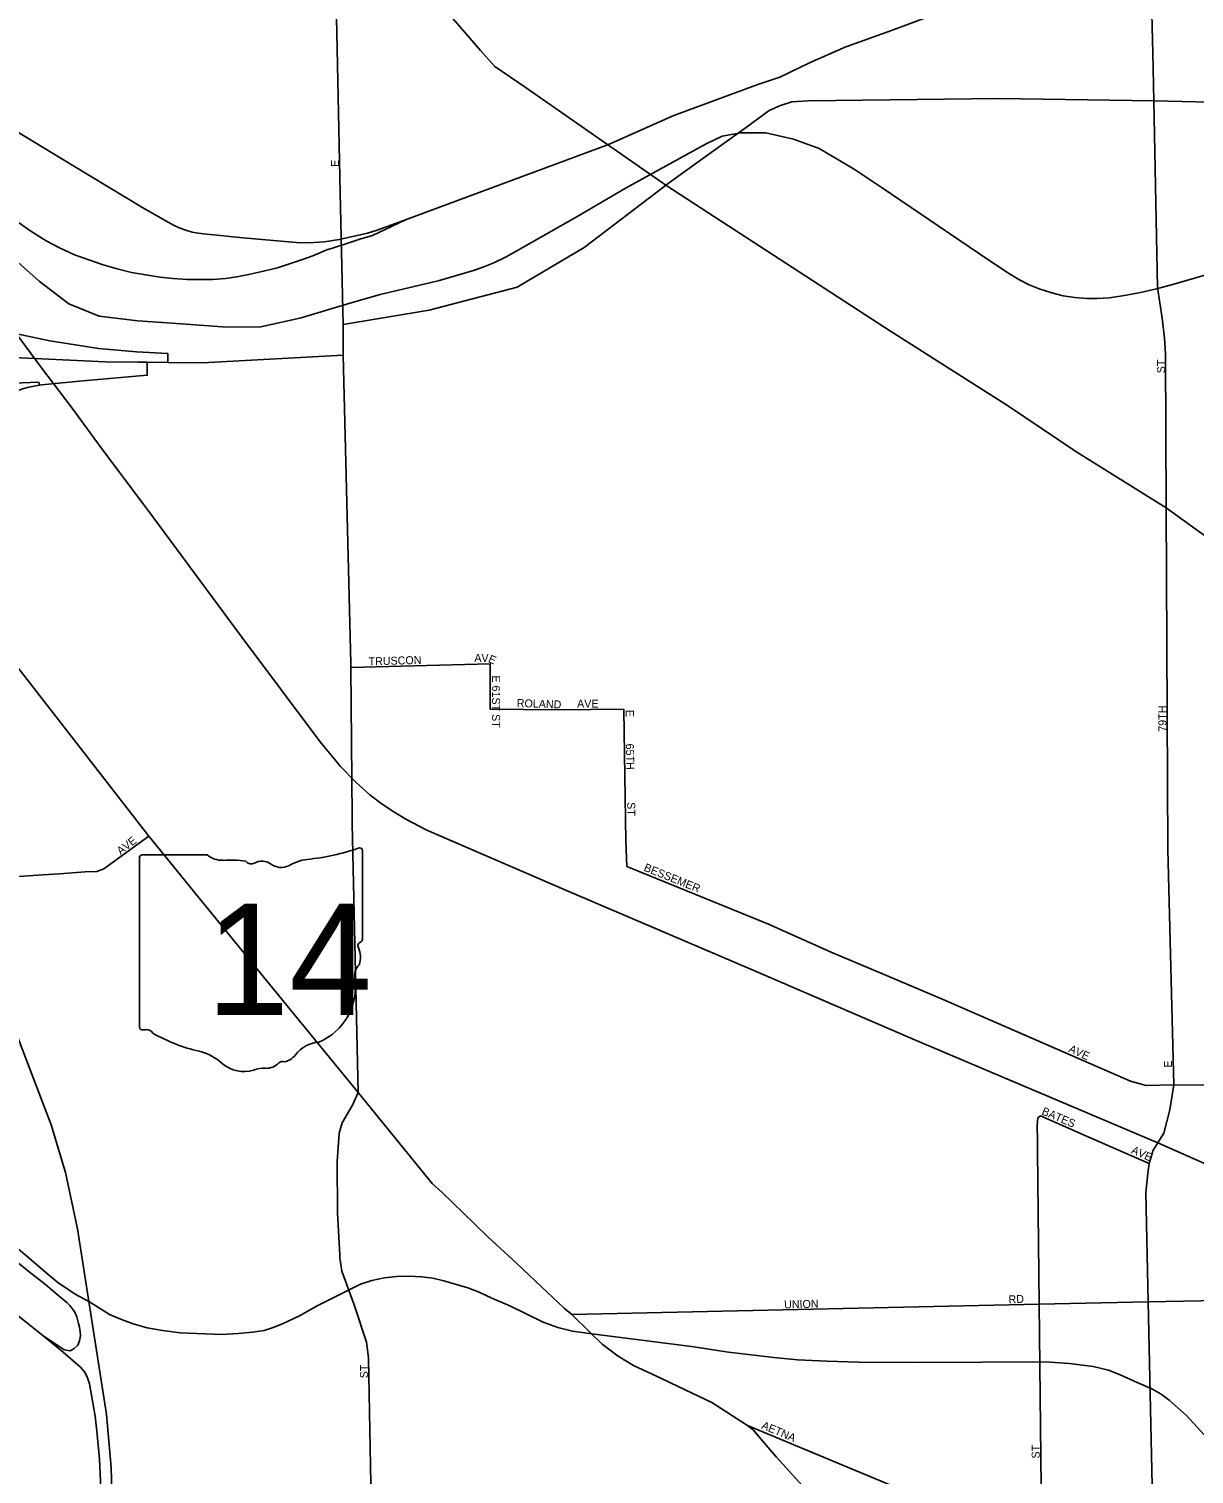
# Model space of a CAD drawing. Extents: x -561 to 1170, y 0 to 846.
# Drawn here: x 268.18 to 287.84, y 250.97 to 275.35 of the extents above; entities that cross this region are included whole.
import ezdxf

# ---------------------------------------------------------------- set-up
doc = ezdxf.new("R2010")
doc.units = 0
for name, color, linetype in [('GM_P_County_Alignment', 7, 'Continuous'), ('GM_X_City_Street', 7, 'Continuous'), ('GM_X_City_Street_Text', 7, 'Continuous'), ('GM_X_Interchange_Ramps', 7, 'Continuous'), ('GM_X_Interstate_Route', 7, 'Continuous'), ('GM_X_Rail_Line', 7, 'Continuous'), ('GM_X_State_Location', 7, 'Continuous'), ('GM_X_State_Route', 7, 'Continuous'), ('GM_X_State_Shield', 7, 'Continuous'), ('GM_X_US_Route', 7, 'Continuous')]:
    doc.layers.add(name, color=color, linetype=linetype)

msp = doc.modelspace()

# ---------------------------------------------------------------- linework, layer by layer
at = {"layer": 'GM_P_County_Alignment'}
msp.add_lwpolyline([(273.482, 270.361), (274.932, 270.603), (276.416, 270.991), (277.547, 271.663), (278.891, 272.688), (278.927, 272.714), (279.692, 273.264), (279.991, 273.477), (280.288, 273.69), (280.673, 273.973), (280.863, 274.059), (281.053, 274.12), (281.33, 274.137), (284.546, 274.173), (287.159, 274.138), (290.025, 274.067)], dxfattribs=at)
at = {"layer": 'GM_X_City_Street'}
for points in [[(273.434, 272.587), (273.318, 277.977), (273.132, 283.304), (273.037, 286.052), (272.983, 290.301), (272.97, 291.367), (272.969, 291.404)], [(287.498, 257.536), (287.498, 257.538), (287.397, 261.505), (287.369, 267.269), (287.36, 269.871), (287.343, 270.131), (287.3, 270.469), (287.222, 270.99), (287.159, 274.138), (287.144, 274.945), (287.117, 276.052), (287.06, 276.294), (286.946, 276.667), (286.888, 276.901), (286.871, 277.102), (286.807, 278.301)], [(273.477, 270.601), (273.434, 272.587)], [(273.61, 264.643), (273.485, 269.848), (273.485, 270.248), (273.482, 270.361), (273.477, 270.601)], [(273.634, 261.948), (273.632, 262.064), (273.611, 264.577), (273.61, 264.643)], [(273.611, 264.577), (275.965, 264.642), (275.965, 264.588)], [(275.965, 264.588), (275.965, 263.879)], [(275.965, 263.879), (275.965, 263.877), (277.091, 263.866), (278.217, 263.872), (278.217, 263.857)], [(278.217, 263.857), (278.252, 261.653), (278.271, 261.221), (278.323, 261.2)], [(273.734, 257.409), (273.634, 261.948)], [(268.695, 261.098), (269.132, 261.128), (269.329, 261.135), (269.446, 261.179), (270.203, 261.73)], [(268.413, 261.079), (268.695, 261.098)], [(278.323, 261.2), (280.659, 260.248), (281.726, 259.772), (282.649, 259.381), (283.618, 258.973), (286.765, 257.597), (287.032, 257.527), (287.498, 257.538)], [(267.409, 261.011), (267.849, 261.041), (268.413, 261.079)], [(287.498, 257.538), (288.021, 257.534), (288.387, 257.543), (289.954, 257.593), (290.044, 257.561), (290.116, 257.459), (291.558, 257.465), (291.591, 256.492), (291.643, 256.424), (292.109, 256.444), (292.519, 256.456), (292.475, 257.061), (292.399, 258.101), (295.762, 258.143)], [(287.062, 256.042), (287.079, 256.211), (287.15, 256.436), (287.329, 256.725), (287.43, 257.117), (287.498, 257.536)], [(273.41, 256.638), (273.416, 256.722), (273.464, 256.896), (273.638, 257.197), (273.734, 257.409)], [(285.196, 256.602), (285.192, 256.854), (285.206, 256.979), (285.248, 257.017), (285.581, 256.871), (286.022, 256.672), (287.079, 256.211)], [(273.425, 254.67), (273.387, 255.371), (273.38, 256.252), (273.41, 256.638)], [(285.27, 249.584), (285.269, 249.71), (285.226, 253.84), (285.199, 256.421), (285.197, 256.519), (285.196, 256.602)], [(287.271, 244.073), (287.898, 245.662), (288.224, 246.528), (288.348, 246.925), (288.028, 247.986), (287.735, 248.712), (287.704, 248.928), (287.735, 249.015), (287.559, 249.234), (287.156, 249.747), (287.067, 253.877), (287.027, 255.72), (287.062, 256.042)], [(273.879, 253.196), (273.879, 253.199), (273.667, 253.827), (273.462, 254.393), (273.428, 254.619), (273.425, 254.67)], [(277.34, 253.662), (285.226, 253.84), (287.067, 253.877), (289.452, 253.925)], [(273.951, 250.806), (273.913, 252.932), (273.879, 253.196)], [(280.304, 251.79), (284.72, 249.952), (285.269, 249.71), (285.314, 249.691), (287.156, 249.747), (288.56, 249.78), (288.562, 249.78)]]:
    msp.add_lwpolyline(points, dxfattribs=at)
at = {"layer": 'GM_X_Interchange_Ramps'}
for points in [[(270.524, 269.724), (270.525, 269.874), (269.995, 269.9), (269.355, 269.961), (268.535, 270.087), (267.65, 270.275), (267.595, 270.287), (267.328, 270.389), (267.108, 270.51), (266.895, 270.656), (266.715, 270.825), (266.549, 271.01), (266.388, 271.244), (266.133, 271.647), (265.699, 272.333), (265.393, 272.845), (265.269, 273.105), (265.17, 273.315), (265.054, 273.576), (264.924, 273.967), (264.838, 273.944)], [(265.022, 271.942), (265.072, 271.942), (265.096, 271.624), (265.139, 271.391), (265.208, 271.132), (265.283, 270.902), (265.389, 270.647), (265.503, 270.453), (265.623, 270.282), (265.756, 270.126), (265.924, 269.978), (265.945, 269.959), (266.014, 269.898), (266.078, 269.841), (266.289, 269.701), (266.485, 269.621), (266.683, 269.556), (266.895, 269.489), (267.177, 269.423), (267.447, 269.391), (267.772, 269.363), (268.069, 269.379), (268.35, 269.388), (268.359, 269.34)], [(266.892, 265.84), (266.998, 265.854), (267.011, 265.855), (266.997, 266.151), (266.952, 266.952), (266.942, 267.44), (266.943, 267.633), (266.944, 267.778), (266.968, 268.061), (267.027, 268.301), (267.101, 268.47), (267.209, 268.66), (267.351, 268.839), (267.491, 268.969), (267.622, 269.066), (267.778, 269.162), (267.956, 269.241), (268.149, 269.3), (268.359, 269.34), (268.392, 269.346), (269.034, 269.41), (270.176, 269.508), (270.175, 269.727)]]:
    msp.add_lwpolyline(points, dxfattribs=at)
at = {"layer": 'GM_X_Interstate_Route'}
for points in [[(265.598, 269.91), (265.847, 269.902), (265.895, 269.9), (265.945, 269.899), (266.014, 269.898), (269.465, 269.734), (270.032, 269.728)], [(270.032, 269.728), (270.175, 269.727), (270.524, 269.724), (271.107, 269.718), (273.485, 269.848)], [(269.461, 246.384), (269.45, 247.031), (269.472, 247.83), (269.535, 249.057), (269.554, 249.438), (269.59, 250.262), (269.568, 251.083), (269.487, 251.978), (269.223, 253.67), (268.998, 255.11), (268.797, 256.059), (268.555, 256.861), (267.902, 258.571), (267.803, 258.875), (267.708, 259.168), (267.579, 259.68), (267.468, 260.382), (267.409, 261.011), (267.349, 261.572)]]:
    msp.add_lwpolyline(points, dxfattribs=at)
at = {"layer": 'GM_X_Rail_Line'}
for points in [[(274.532, 272.13), (277.959, 273.399), (279.06, 273.889), (280.481, 274.414), (280.848, 274.536), (281.353, 274.779), (281.966, 275.046), (282.732, 275.323), (283.444, 275.588), (283.614, 275.646), (283.794, 275.706), (283.956, 275.758), (284.123, 275.81), (284.308, 275.857), (284.475, 275.902), (284.791, 275.967), (284.993, 276.006), (285.523, 276.083), (286.531, 276.223), (287.281, 276.324), (287.886, 276.4)], [(274.532, 272.13), (274.054, 271.957), (273.891, 271.905), (273.417, 271.795), (273.166, 271.76), (272.991, 271.745), (272.76, 271.743), (271.796, 271.826), (271.124, 271.893), (271.037, 271.904), (270.937, 271.92), (270.826, 271.952), (270.716, 271.993), (270.619, 272.04), (270.528, 272.091), (270.112, 272.328), (268.924, 273.048), (267.287, 274.036)], [(290.364, 271.874), (287.5, 271.045), (287.207, 270.966), (286.937, 270.905), (286.632, 270.847), (286.408, 270.814), (286.205, 270.801), (286.037, 270.801), (285.826, 270.819), (285.633, 270.849), (285.437, 270.896), (285.228, 270.967), (285.057, 271.035), (284.88, 271.124), (284.699, 271.233), (284.2, 271.569), (283.381, 272.122), (282.578, 272.668), (282.104, 272.986), (281.514, 273.333), (281.083, 273.49), (280.612, 273.595), (280.194, 273.595), (279.88, 273.543), (279.606, 273.412), (278.258, 272.669), (277.44, 272.192), (276.661, 271.747), (276.376, 271.582), (276.22, 271.499), (276.024, 271.405), (275.854, 271.338), (275.697, 271.281), (275.489, 271.217), (275.087, 271.1), (274.109, 270.867), (273.577, 270.717), (272.773, 270.474), (272.093, 270.326), (271.522, 270.316), (270.754, 270.375), (270.016, 270.425), (269.366, 270.503), (268.854, 270.71), (268.352, 271.094), (267.683, 271.685)], [(268.003, 272.086), (268.215, 271.937), (268.47, 271.774), (268.697, 271.654), (268.95, 271.54), (269.206, 271.446), (269.435, 271.371), (269.671, 271.304), (269.91, 271.243), (270.152, 271.2), (270.388, 271.163), (270.615, 271.138), (270.851, 271.122), (271.084, 271.12), (271.278, 271.124), (271.499, 271.141), (271.69, 271.17), (271.887, 271.204), (272.141, 271.264), (272.375, 271.318), (272.778, 271.452), (272.972, 271.522), (273.206, 271.622), (273.321, 271.656), (273.559, 271.738), (273.763, 271.802), (273.977, 271.866), (274.19, 271.967), (274.532, 272.13)], [(267.047, 271.442), (268.412, 269.609), (268.891, 268.973), (269.447, 268.219), (270.175, 267.246), (271.773, 265.091), (273.094, 263.322), (273.438, 262.91), (273.703, 262.64), (273.935, 262.427), (274.139, 262.274), (274.335, 262.144), (274.538, 262.018), (274.895, 261.836), (277.253, 260.818), (280.49, 259.432), (283.099, 258.309), (287.229, 256.558), (289.084, 255.741)], [(267.371, 255.305), (268.499, 254.345), (268.667, 254.205), (268.962, 254.005), (269.202, 253.879), (269.54, 253.661), (269.744, 253.579), (269.937, 253.509), (270.178, 253.441), (270.432, 253.396), (270.735, 253.355), (271.436, 253.327), (271.712, 253.343), (271.954, 253.364), (272.148, 253.394), (272.32, 253.45), (272.468, 253.513), (272.746, 253.642), (273.045, 253.808), (273.507, 254.043), (273.776, 254.176), (273.965, 254.238), (274.178, 254.281), (274.383, 254.302), (274.596, 254.31), (274.808, 254.299), (274.995, 254.279), (275.183, 254.232), (275.587, 254.113), (275.779, 254.041), (275.99, 253.941), (276.297, 253.81), (276.559, 253.681), (276.86, 253.536), (277.106, 253.443), (277.35, 253.382), (277.677, 253.335), (279.359, 253.123), (279.985, 253.03), (280.749, 252.94), (281.146, 252.899), (281.642, 252.874), (282.185, 252.858), (283.198, 252.852), (285.329, 252.868), (285.738, 252.839), (286.135, 252.786), (286.395, 252.723), (286.581, 252.65), (286.878, 252.516), (287.124, 252.411), (287.284, 252.321), (287.417, 252.219), (287.714, 251.96), (288.011, 251.633)], [(268.413, 253.307), (268.775, 253.069), (268.877, 253.052), (268.94, 253.082), (269.007, 253.145), (269.037, 253.218), (269.051, 253.304), (269.046, 253.369), (269.034, 253.451), (269.016, 253.512), (268.992, 253.627), (268.949, 253.714), (268.873, 253.814), (268.819, 253.864), (268.66, 254.002), (268.458, 254.168), (268.186, 254.381), (267.76, 254.73)], [(267.914, 253.706), (268.413, 253.307)], [(268.413, 253.307), (268.759, 253.026), (269.049, 252.778), (269.117, 252.697), (269.166, 252.61), (269.204, 252.496), (269.3, 251.946), (269.328, 251.693), (269.37, 251.225), (269.389, 250.86), (269.394, 250.422)]]:
    msp.add_lwpolyline(points, dxfattribs=at)
at = {"layer": 'GM_X_State_Route'}
for points in [[(266.96, 265.902), (266.998, 265.854), (267.856, 264.75), (268.11, 264.423), (270.203, 261.73), (271.112, 260.618)], [(271.112, 260.618), (272.465, 258.962)], [(272.465, 258.962), (273.734, 257.409), (274.985, 255.874), (275.16, 255.714), (275.51, 255.377), (275.925, 254.976), (276.411, 254.526), (276.831, 254.131), (277.214, 253.772), (277.34, 253.662), (277.65, 253.359), (277.855, 253.161), (278.123, 252.959), (278.38, 252.803), (278.853, 252.584), (279.137, 252.448)], [(279.137, 252.448), (279.704, 252.177), (280.304, 251.79), (280.402, 251.718), (280.653, 251.421)], [(280.653, 251.421), (280.792, 251.258), (281.443, 250.545), (281.886, 250.047), (282.285, 249.607), (282.663, 249.184), (282.846, 248.984), (282.881, 248.945), (283.117, 248.686), (283.151, 248.649)]]:
    msp.add_lwpolyline(points, dxfattribs=at)
at = {"layer": 'GM_X_State_Shield'}
for p, q in [((270.048, 261.367), (270.048, 258.514)), ((271.186, 261.416), (270.085, 261.416)), ((273.807, 259.994), (273.807, 261.486)), ((273.807, 259.994), (273.807, 259.994))]:
    msp.add_line(p, q, dxfattribs=at)
for centre, radius, start, end in [((270.091, 261.373), 0.0435, 98.1301, 188.1301), ((271.448, 261.747), 0.422, 231.6195, 271.1119), ((272.977, 260.544), 0.802, 97.3462, 120.7689), ((272.468, 265.305), 3.986, 275.8445, 288.9065), ((273.765, 261.493), 0.0418, 351.8621, 97.738), ((271.588, 259.814), 1.516, 80.4867, 94.9883), ((271.932, 261.387), 0.122, 219.7921, 297.1024), ((272.111, 261.058), 0.253, 54.4667, 119.1411), ((272.438, 261.51), 0.305, 233.8562, 294.8282), ((273.797, 259.884), 0.0648, 107.944, 210.337), ((273.762, 259.988), 0.0448, 289.6038, 7.7341), ((273.385, 259.696), 0.389, 340.033, 23.6496), ((273.957, 259.369), 0.283, 136.8065, 186.9296), ((272.691, 259.18), 0.997, 292.3089, 8.9858), ((270.092, 258.507), 0.0439, 171.9584, 258.3066), ((270.098, 258.799), 0.335, 267.339, 280.6039), ((270.167, 258.349), 0.121, 29.7484, 93.2717), ((271.693, 260.912), 2.879, 240.4129, 257.1985), ((273.112, 257.713), 0.546, 94.4031, 142.5768), ((270.835, 257.232), 0.901, 47.1842, 75.836), ((272.457, 257.845), 0.0857, 65.7517, 132.6484), ((272.42, 258.237), 0.322, 282.8732, 323.2771), ((271.809, 258.335), 0.572, 230.7004, 286.2918), ((272.139, 257.348), 0.47, 85.6951, 111.2099), ((272.181, 258.121), 0.305, 268.777, 315.5493)]:
    msp.add_arc(centre, radius, start, end, dxfattribs=at)
at = {"layer": 'GM_X_US_Route'}
for points in [[(273.318, 277.977), (273.358, 277.821), (273.447, 277.668), (273.712, 277.39), (274.153, 276.896), (275.798, 274.984), (276.044, 274.717), (276.552, 274.364)], [(276.552, 274.364), (278.927, 272.714), (279.636, 272.254)], [(279.636, 272.254), (282.72, 270.252), (284.706, 268.986), (285.843, 268.223), (287.369, 267.269), (287.976, 266.83), (288.357, 266.584), (288.549, 266.46)]]:
    msp.add_lwpolyline(points, dxfattribs=at)

# ---------------------------------------------------------------- texts
at = {"layer": 'GM_X_City_Street_Text'}
for s, rotation, p in [('E', 90, (273.413, 273.022)), ('ST', 90, (287.349, 269.541)), ('TRUSCON', 1.7615, (273.913, 264.612)), ('A', 359.6721, (275.696, 264.672)), ('V', 359.6502, (275.815, 264.671)), ('E', 336.7225, (275.919, 264.673)), ('E 61ST ST', 270, (275.995, 264.444)), ('ROLAND', 357.9877, (276.41, 263.912)), ('AVE', 0, (277.43, 263.9)), ('E', 270, (278.252, 263.862)), ('79TH', 90, (287.372, 263.494)), ('65TH', 271.3632, (278.252, 263.293)), ('ST', 270, (278.276, 262.306)), ('AVE', 38.0509, (269.728, 261.411)), ('BESSEMER', 338.0503, (278.545, 261.153)), ('AVE', 335.2238, (285.71, 258.1)), ('E', 90, (287.467, 257.827)), ('BATES', 336.9771, (285.257, 257.043)), ('AVE', 336.0428, (286.767, 256.389)), ('UNION', 1.2724, (280.923, 253.766)), ('RD', 3.0116, (284.712, 253.849)), ('ST', 90, (273.901, 252.588)), ('AETNA', 337.2835, (280.529, 251.744)), ('ST', 90, (285.234, 251.234))]:
    msp.add_text(s, height=0.135, rotation=rotation, dxfattribs=at).set_placement(p)
at = {"layer": 'GM_X_State_Location'}
for s in ['s', 'r']:
    msp.add_text(s, height=0.0027, dxfattribs=at).set_placement((271.885, 259.75))
msp.add_text('14', height=0.0027, rotation=0, dxfattribs=at).set_placement((271.205, 259.554))
at = {"layer": 'GM_X_State_Shield'}
msp.add_text('14', height=1.8795, dxfattribs=at).set_placement((271.173, 258.715))

doc.saveas('drawing.dxf')
